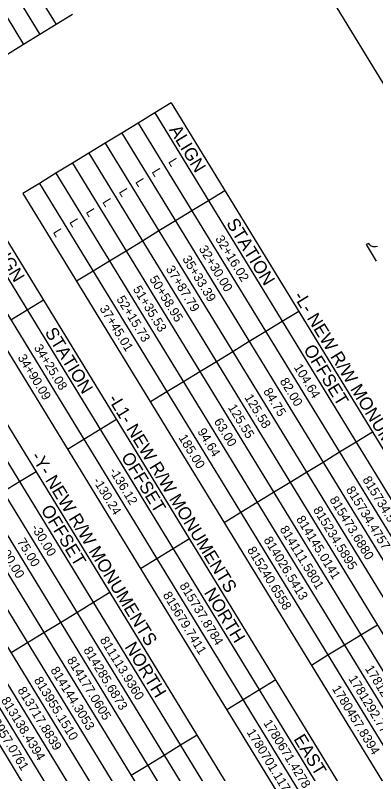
# Model space of a CAD drawing. Extents: x 1753086 to 1770987, y 792577 to 812636.
# Drawn here: x 1762877 to 1764623, y 804785 to 808460 of the extents above; entities that cross this region are included whole.
import ezdxf

# ---------------------------------------------------------------- set-up
doc = ezdxf.new("R2010")
doc.units = 0
for name, color, linetype in [('CTL Sheet Border CELL', 7, 'Continuous'), ('CTL Sheet Notes CELL', 7, 'Continuous'), ('CTL Sheet Table Cell', 7, 'Continuous'), ('CTL Sheet Text', 7, 'Continuous'), ('Sheet Data Field CELL', 7, 'Continuous')]:
    doc.layers.add(name, color=color, linetype=linetype)

msp = doc.modelspace()

# ---------------------------------------------------------------- linework, layer by layer
at = {"layer": 'CTL Sheet Border CELL'}
msp.add_lwpolyline([(1770671.7, 798289.4), (1762511, 811645.8), (1753161.6, 805933.4), (1761322.3, 792577)], close=True, dxfattribs=at)
at = {"layer": 'CTL Sheet Table Cell'}
for p, q in [((1761726.7, 810621.7), (1763075.6, 808414)), ((1761647.9, 810573.5), (1762996.8, 808365.8)), ((1761569, 810525.3), (1762917.9, 808317.6)), ((1763154.5, 808462.2), (1763075.6, 808414)), ((1763075.6, 808414), (1762996.8, 808365.8)), ((1762996.8, 808365.8), (1762917.9, 808317.6)), ((1762917.9, 808317.6), (1762839.1, 808269.4)), ((1763632.3, 808034.5), (1763552.6, 807985.8)), ((1763632.3, 808034.5), (1765451.3, 805057.5)), ((1763552.6, 807985.8), (1763472.8, 807937.1)), ((1763552.6, 807985.8), (1765371.6, 805008.7)), ((1763472.8, 807937.1), (1763393.1, 807888.4)), ((1763472.8, 807937.1), (1765291.8, 804960)), ((1763393.1, 807888.4), (1763313.3, 807839.7)), ((1763393.1, 807888.4), (1765212.1, 804911.3)), ((1763313.3, 807839.7), (1763233.6, 807790.9)), ((1763313.3, 807839.7), (1765132.3, 804862.6)), ((1763233.6, 807790.9), (1763153.9, 807742.2)), ((1763233.6, 807790.9), (1765052.6, 804813.9)), ((1763153.9, 807742.2), (1763074.1, 807693.5)), ((1763153.9, 807742.2), (1764972.8, 804765.1)), ((1763074.1, 807693.5), (1762994.4, 807644.8)), ((1763074.1, 807693.5), (1764893.1, 804716.4)), ((1762994.4, 807644.8), (1762914.6, 807596)), ((1762994.4, 807644.8), (1764813.4, 804667.7)), ((1762914.6, 807596), (1764733.6, 804619)), ((1763892.2, 807609.2), (1763812.4, 807560.5)), ((1763812.4, 807560.5), (1763732.7, 807511.8)), ((1763732.7, 807511.8), (1763652.9, 807463.1)), ((1762756.9, 807499.7), (1764555.5, 804556.1)), ((1762678.1, 807451.5), (1764476.6, 804507.9)), ((1763652.9, 807463.1), (1763573.2, 807414.4)), ((1762599.2, 807403.3), (1764397.8, 804459.7)), ((1763573.2, 807414.4), (1763493.5, 807365.6)), ((1763493.5, 807365.6), (1763413.7, 807316.9)), ((1762520.4, 807355.2), (1764318.9, 804411.5)), ((1763413.7, 807316.9), (1763334, 807268.2)), ((1762360.9, 807257.7), (1764179.9, 804280.6)), ((1763334, 807268.2), (1763254.2, 807219.5)), ((1763254.2, 807219.5), (1763174.5, 807170.7)), ((1762281.2, 807209), (1764100.2, 804231.9)), ((1762201.4, 807160.3), (1764020.4, 804183.2)), ((1762121.7, 807111.5), (1763940.7, 804134.5)), ((1763013.9, 807079.2), (1762935, 807031)), ((1762041.9, 807062.8), (1763860.9, 804085.7)), ((1761962.2, 807014.1), (1763781.2, 804037)), ((1762935, 807031), (1762856.2, 806982.8)), ((1764249.5, 807024.5), (1764169.7, 806975.7)), ((1761882.4, 806965.4), (1763701.4, 803988.3)), ((1764169.7, 806975.7), (1764090, 806927)), ((1764090, 806927), (1764010.2, 806878.3)), ((1761802.7, 806916.7), (1763621.7, 803939.6)), ((1761723, 806867.9), (1763542, 803890.9)), ((1764010.2, 806878.3), (1763930.5, 806829.6)), ((1761643.2, 806819.2), (1763462.2, 803842.1)), ((1763930.5, 806829.6), (1763850.8, 806780.9)), ((1763850.8, 806780.9), (1763771, 806732.1)), ((1763771, 806732.1), (1763691.3, 806683.4)), ((1763691.3, 806683.4), (1763611.5, 806634.7)), ((1763611.5, 806634.7), (1763531.8, 806586)), ((1763367.2, 806501), (1763288.3, 806452.8)), ((1763288.3, 806452.8), (1763209.5, 806404.6)), ((1764606.8, 806439.7), (1764527, 806391)), ((1763209.5, 806404.6), (1763130.6, 806356.4)), ((1764527, 806391), (1764447.3, 806342.2)), ((1764447.3, 806342.2), (1764367.5, 806293.5)), ((1764367.5, 806293.5), (1764287.8, 806244.8)), ((1762978.1, 806247.6), (1762898.3, 806198.9)), ((1764287.8, 806244.8), (1764208.1, 806196.1)), ((1762898.3, 806198.9), (1762818.6, 806150.2)), ((1764208.1, 806196.1), (1764128.3, 806147.3)), ((1764128.3, 806147.3), (1764048.6, 806098.6)), ((1764048.6, 806098.6), (1763968.8, 806049.9)), ((1763968.8, 806049.9), (1763889.1, 806001.2)), ((1763720.4, 805922.7), (1763641.6, 805874.6)), ((1763641.6, 805874.6), (1763562.7, 805826.4)), ((1763562.7, 805826.4), (1763483.9, 805778.2)), ((1763335.4, 805662.9), (1763255.6, 805614.1)), ((1763255.6, 805614.1), (1763175.9, 805565.4)), ((1763175.9, 805565.4), (1763096.1, 805516.7)), ((1763096.1, 805516.7), (1763016.4, 805468)), ((1764630.3, 805505), (1764550.6, 805456.2)), ((1763016.4, 805468), (1762936.6, 805419.2)), ((1764550.6, 805456.2), (1764470.8, 805407.5)), ((1762936.6, 805419.2), (1762856.9, 805370.5)), ((1764470.8, 805407.5), (1764391.1, 805358.8)), ((1764391.1, 805358.8), (1764311.4, 805310.1)), ((1764138, 805239.4), (1764059.1, 805191.2)), ((1764059.1, 805191.2), (1763980.3, 805143.1)), ((1763980.3, 805143.1), (1763901.4, 805094.9)), ((1763757.6, 804971.7), (1763677.9, 804923)), ((1763677.9, 804923), (1763598.1, 804874.3)), ((1763598.1, 804874.3), (1763518.4, 804825.6)), ((1763518.4, 804825.6), (1763438.7, 804776.9))]:
    msp.add_line(p, q, dxfattribs=at)
at = {"layer": 'Sheet Data Field CELL'}
msp.add_lwpolyline([(1764630.2, 807339.8), (1764620.7, 807337.7), (1764620.5, 807337.6), (1764619.8, 807337.5), (1764616.3, 807337.5), (1764611.2, 807337.6), (1764610, 807337.6), (1764607.5, 807338.6), (1764602.1, 807340.8), (1764601.1, 807341.2), (1764597.3, 807344.6), (1764594.4, 807347.2), (1764594, 807347.5), (1764589.6, 807353), (1764575.5, 807348.3), (1764624.9, 807267.3)], dxfattribs=at)

# ---------------------------------------------------------------- texts
at = {"layer": 'CTL Sheet Notes CELL'}
for s, height, p in [('ALIGN', 62.3, (1763620.6, 807904.4)), ('STATION', 62.3, (1763896.9, 807452.1)), ('ALIGN', 61.6, (1762745.3, 807371)), ('-L- NEW R/W MONUMENTS', 62.3, (1764222.1, 807099.1)), ('STATION', 61.6, (1763018.6, 806923.8)), ('OFFSET', 62.3, (1764270.4, 806840.9)), ('-L1- NEW R/W MONUMENTS', 61.6, (1763324.2, 806600.9)), ('OFFSET', 61.6, (1763387.8, 806319.5)), ('-Y- NEW R/W MONUMENTS', 62.3, (1762950.7, 806322.3)), ('OFFSET', 62.3, (1762999, 806064.1)), ('NORTH', 61.6, (1763789.1, 805662.6)), ('NORTH', 62.3, (1763404.8, 805399.8)), ('EAST', 61.6, (1764222.6, 804953.2))]:
    msp.add_text(s, height=height, rotation=301.4249, dxfattribs=at).set_placement(p)
at = {"layer": 'CTL Sheet Text'}
for s, height, p in [('L', 44.5, (1763616, 807749.8)), ('L', 44.5, (1763536.2, 807701)), ('L', 44.5, (1763456.5, 807652.3)), ('L', 44.5, (1763376.7, 807603.6)), ('L', 44.5, (1763297, 807554.9)), ('L', 44.5, (1763217.2, 807506.2)), ('L', 44.5, (1763137.5, 807457.4)), ('L', 44.5, (1763057.8, 807408.7)), ('32+16.02', 44.5, (1763844, 807376.6)), ('32+30.00', 44.5, (1763764.2, 807327.9)), ('35+33.39', 44.5, (1763684.5, 807279.1)), ('37+87.79', 44.5, (1763604.7, 807230.4)), ('50+58.95', 44.5, (1763525, 807181.7)), ('51+35.53', 44.5, (1763445.3, 807133)), ('52+15.73', 44.5, (1763365.5, 807084.3)), ('37+45.01', 44.5, (1763283.8, 807038.8)), ('34+25.08', 44, (1762966.2, 806849.1)), ('34+90.09', 44, (1762887.4, 806800.9)), ('104.64', 44.5, (1764224.3, 806754.1)), ('82.00', 44.5, (1764156.1, 806686.6)), ('84.75', 44.5, (1764076.3, 806637.8)), ('125.58', 44.5, (1763985.1, 806608)), ('125.55', 44.5, (1763905.3, 806559.2)), ('63.00', 44.5, (1763837.1, 806491.7)), ('94.64', 44.5, (1763757.4, 806443)), ('185.00', 44.5, (1763666.1, 806413.1)), ('-136.12', 44, (1763330.9, 806252.3)), ('815734.5483', 44.5, (1764556.5, 806210.4)), ('-130.24', 44, (1763252, 806204.1)), ('815734.4757', 44.5, (1764476.8, 806161.6)), ('815473.6880', 44.5, (1764397.1, 806112.9)), ('815234.5895', 44.5, (1764317.3, 806064.2)), ('814145.0141', 44.5, (1764235.6, 806018.8)), ('-30.00', 44.5, (1762952.9, 805977.3)), ('814111.5801', 44.5, (1764155.8, 805970)), ('75.00', 44.5, (1762884.7, 805909.7)), ('814026.5413', 44.5, (1764078.1, 805918)), ('-100.00', 44.5, (1762781.9, 805898.7)), ('815240.6558', 44.5, (1763998.3, 805869.3)), ('815737.8784', 44, (1763670.8, 805696)), ('815679.7411', 44, (1763589.9, 805651.1)), ('811113.9360', 44.5, (1763285.1, 805433.5)), ('814285.6873', 44.5, (1763205.4, 805384.8)), ('814177.0605', 44.5, (1763125.6, 805336.1)), ('1781278.5970', 44.5, (1764568.6, 805294.5)), ('814144.3053', 44.5, (1763045.9, 805287.4)), ('813955.1510', 44.5, (1762966.2, 805238.6)), ('1781292.7785', 44.5, (1764488.8, 805245.8)), ('813717.8839', 44.5, (1762886.4, 805189.9)), ('1780457.8394', 44.5, (1764409.1, 805197)), ('813138.4394', 44.5, (1762806.7, 805141.2)), ('812957.0761', 44.5, (1762726.9, 805092.5)), ('1780671.4278', 44, (1764076.9, 805031.3)), ('1780701.1171', 44, (1763996.1, 804986.4))]:
    msp.add_text(s, height=height, rotation=301.4249, dxfattribs=at).set_placement(p)

doc.saveas('drawing.dxf')
